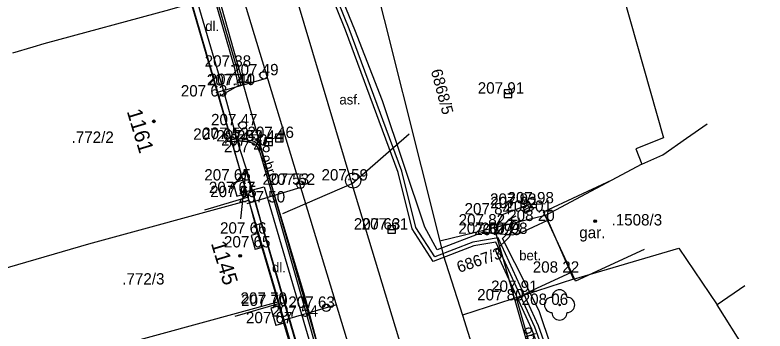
# Model space of a CAD drawing. Extents: x -524633 to -524336, y -1187893 to -1187683.
# Drawn here: x -524519.98 to -524470.48, y -1187820.09 to -1187799.22 of the extents above; entities that cross this region are included whole.
import ezdxf

# ---------------------------------------------------------------- set-up
doc = ezdxf.new("R2010")
doc.units = 0
for name, color, linetype in [('Hranice parcel', 7, 'Continuous'), ('Parcelní čísla', 7, 'Continuous'), ('Vrstva 1', 7, 'Continuous'), ('Vrstva 10', 7, 'Continuous'), ('Vrstva 11', 7, 'Continuous'), ('Vrstva 22', 7, 'Continuous'), ('Vrstva 24', 7, 'Continuous'), ('Vrstva 27', 7, 'Continuous'), ('Vrstva 28', 7, 'Continuous'), ('Vrstva 3', 7, 'Continuous'), ('Vrstva 36', 7, 'Continuous'), ('Vrstva 39', 7, 'Continuous'), ('Vrstva 4', 7, 'Continuous'), ('Vrstva 40', 7, 'Continuous'), ('Vrstva 41', 7, 'Continuous'), ('Vrstva 47', 7, 'Continuous'), ('Vrstva 5', 7, 'Continuous'), ('Vrstva 52', 7, 'Continuous'), ('Vrstva 53', 7, 'Continuous'), ('Vrstva 54', 7, 'Continuous'), ('Vrstva 55', 7, 'Continuous'), ('Vrstva 56', 7, 'Continuous'), ('Vrstva 58', 7, 'Continuous')]:
    doc.layers.add(name, color=color, linetype=linetype)

msp = doc.modelspace()

# ---------------------------------------------------------------- linework, layer by layer
at = {"layer": 'Hranice parcel'}
for p, q in [((-524504.56, -1187811.45), (-524508.34, -1187798.46)), ((-524478.61, -1187809.07), (-524484.96, -1187812.46)), ((-524502.57, -1187818.16), (-524504.56, -1187811.45)), ((-524484.96, -1187812.46), (-524491.95, -1187814.16)), ((-524484.96, -1187812.46), (-524484.74, -1187812.94)), ((-524484.74, -1187812.94), (-524483.13, -1187816.67)), ((-524483.13, -1187816.67), (-524490.45, -1187819.04)), ((-524500.33, -1187825.89), (-524502.57, -1187818.16)), ((-524470.48, -1187823.34), (-524473.64, -1187818.37))]:
    msp.add_line(p, q, dxfattribs=at)
for points in [[(-524504.01, -1187770.49), (-524496.85, -1187794.59), (-524491.95, -1187814.16)], [(-524480.71, -1187794.88), (-524477.19, -1187807.33), (-524479.01, -1187808.05), (-524478.61, -1187809.07)], [(-524508.34, -1187798.46), (-524509.78, -1187798.88), (-524518.07, -1187801.13)], [(-524518.07, -1187801.13), (-524518.81, -1187801.35), (-524520.15, -1187801.74)], [(-524478.61, -1187809.07), (-524477.23, -1187808.46), (-524475.66, -1187807.35), (-524474.304, -1187806.397)], [(-524526.11, -1187817.52), (-524521.55, -1187816.2), (-524515.1, -1187814.33), (-524504.56, -1187811.45)], [(-524491.95, -1187814.16), (-524491.72, -1187815.07), (-524490.45, -1187819.04)], [(-524483.13, -1187816.67), (-524476.17, -1187814.61), (-524473.64, -1187818.37)], [(-524471.818, -1187817.116), (-524473.64, -1187818.37)], [(-524502.57, -1187818.16), (-524513.11, -1187821.06), (-524515.74, -1187821.78), (-524520.23, -1187823.1), (-524526.74, -1187825.01)], [(-524490.45, -1187819.04), (-524486.12, -1187832.88), (-524481.69, -1187847.02)]]:
    msp.add_lwpolyline(points, dxfattribs=at)
at = {"layer": 'Vrstva 1'}
for p, q in [((-524505.37, -1187802.63), (-524505.37, -1187802.63)), ((-524503.56, -1187803.2), (-524503.56, -1187803.2)), ((-524505.23, -1187803.87), (-524505.23, -1187803.87)), ((-524505.08, -1187803.84), (-524505.08, -1187803.84)), ((-524506.54, -1187804.6), (-524506.54, -1187804.6)), ((-524487.44, -1187804.41), (-524487.44, -1187804.41)), ((-524504.95, -1187806.5), (-524504.95, -1187806.5)), ((-524505.72, -1187807.46), (-524505.72, -1187807.46)), ((-524505.13, -1187807.4), (-524505.13, -1187807.4)), ((-524504.19, -1187807.57), (-524504.19, -1187807.57)), ((-524503.24, -1187807.58), (-524503.24, -1187807.58)), ((-524502.53, -1187807.34), (-524502.53, -1187807.34)), ((-524503.88, -1187807.84), (-524503.88, -1187807.84)), ((-524503.69, -1187808.28), (-524503.69, -1187808.28)), ((-524504.99, -1187810.15), (-524504.99, -1187810.15)), ((-524497.66, -1187810.15), (-524497.66, -1187810.15)), ((-524501.14, -1187810.43), (-524501.14, -1187810.43)), ((-524501.14, -1187810.44), (-524501.14, -1187810.44)), ((-524504.69, -1187810.98), (-524504.69, -1187810.98)), ((-524504.6, -1187811.25), (-524504.6, -1187811.25)), ((-524502.72, -1187811.6), (-524502.72, -1187811.6)), ((-524484.98, -1187811.66), (-524484.98, -1187811.66)), ((-524486.13, -1187811.75), (-524486.13, -1187811.75)), ((-524486.11, -1187811.98), (-524486.11, -1187811.98)), ((-524487.81, -1187812.39), (-524487.81, -1187812.39)), ((-524485.11, -1187812.21), (-524485.11, -1187812.21)), ((-524488.2, -1187813.12), (-524488.2, -1187813.12)), ((-524484.93, -1187812.83), (-524484.93, -1187812.83)), ((-524503.95, -1187813.66), (-524503.95, -1187813.66)), ((-524495.12, -1187813.39), (-524495.12, -1187813.39)), ((-524495.1, -1187813.39), (-524495.1, -1187813.39)), ((-524488.22, -1187813.67), (-524488.22, -1187813.67)), ((-524486.72, -1187813.68), (-524486.72, -1187813.68)), ((-524488.27, -1187813.76), (-524488.27, -1187813.76)), ((-524487.17, -1187813.76), (-524487.17, -1187813.76)), ((-524503.69, -1187814.57), (-524503.69, -1187814.57)), ((-524483.31, -1187816.24), (-524483.31, -1187816.24)), ((-524482.99, -1187816.8), (-524482.99, -1187816.8)), ((-524486.06, -1187817.51), (-524486.06, -1187817.51)), ((-524486.98, -1187818.07), (-524486.98, -1187818.07)), ((-524502.6, -1187818.29), (-524502.6, -1187818.29)), ((-524502.56, -1187818.44), (-524502.56, -1187818.44)), ((-524499.44, -1187818.56), (-524499.44, -1187818.56)), ((-524484.04, -1187818.37), (-524484.04, -1187818.37)), ((-524502.24, -1187819.58), (-524502.24, -1187819.58)), ((-524500.55, -1187819.15), (-524500.55, -1187819.15))]:
    msp.add_line(p, q, dxfattribs=at)
at = {"layer": 'Vrstva 10'}
msp.add_line((-524506.539, -1187804.6), (-524505.229, -1187803.87), dxfattribs=at)
for points in [[(-524505.229, -1187803.87), (-524505.079, -1187803.84), (-524505.369, -1187802.63), (-524510.679, -1187784.37), (-524510.92, -1187783.49)], [(-524502.719, -1187811.6), (-524503.689, -1187808.28), (-524503.879, -1187807.84), (-524504.189, -1187807.57), (-524505.129, -1187807.4), (-524505.72, -1187807.46)], [(-524500.549, -1187819.15), (-524502.719, -1187811.6)], [(-524488.219, -1187813.67), (-524488.199, -1187813.12), (-524487.809, -1187812.39), (-524486.129, -1187811.75), (-524484.979, -1187811.66)], [(-524485.629, -1187822.8), (-524486.979, -1187818.07), (-524488.219, -1187813.67)], [(-524497.64, -1187829.21), (-524500.549, -1187819.15)]]:
    msp.add_lwpolyline(points, dxfattribs=at)
at = {"layer": 'Vrstva 11'}
for p, q in [((-524500.674, -1187819.186), (-524502.844, -1187811.636)), ((-524497.765, -1187829.246), (-524500.674, -1187819.186))]:
    msp.add_line(p, q, dxfattribs=at)
for points in [[(-524505.229, -1187803.87), (-524505.495, -1187802.663), (-524510.75, -1187784.44), (-524511.045, -1187783.524)], [(-524502.844, -1187811.636), (-524503.812, -1187808.324), (-524503.987, -1187807.919), (-524504.247, -1187807.692), (-524505.134, -1187807.531), (-524505.707, -1187807.589)], [(-524484.843, -1187812.789), (-524486.719, -1187813.68), (-524487.169, -1187813.76), (-524488.219, -1187813.67)], [(-524486.864, -1187818), (-524486.06, -1187817.51), (-524483.259, -1187816.217)], [(-524485.504, -1187822.764), (-524486.864, -1187818), (-524486.979, -1187818.07)]]:
    msp.add_lwpolyline(points, dxfattribs=at)
at = {"layer": 'Vrstva 22'}
msp.add_circle((-524484.04, -1187818.37), 0.05, dxfattribs=at)
for centre, start, end in [((-524484.04, -1187817.87), 0, 180), ((-524484.54, -1187818.37), 90, 270), ((-524483.54, -1187818.37), 270, 90), ((-524484.04, -1187818.87), 180, 0)]:
    msp.add_arc(centre, 0.5, start, end, dxfattribs=at)
at = {"layer": 'Vrstva 24'}
msp.add_lwpolyline([(-524486.389, -1187812.11), (-524486.299, -1187812.3), (-524485.75, -1187812.05), (-524485.84, -1187811.85), (-524486.389, -1187812.11)], dxfattribs=at)
at = {"layer": 'Vrstva 27'}
for p, q in [((-524487.69, -1187804.41), (-524487.19, -1187804.41)), ((-524503.489, -1187807.58), (-524502.989, -1187807.58)), ((-524502.78, -1187807.34), (-524502.28, -1187807.34)), ((-524495.369, -1187813.39), (-524494.869, -1187813.39))]:
    msp.add_line(p, q, dxfattribs=at)
for points in [[(-524487.69, -1187804.66), (-524487.19, -1187804.66), (-524487.19, -1187804.16), (-524487.69, -1187804.16)], [(-524502.78, -1187807.59), (-524502.28, -1187807.59), (-524502.28, -1187807.09), (-524502.78, -1187807.09)], [(-524503.489, -1187807.83), (-524502.989, -1187807.83), (-524502.989, -1187807.33), (-524503.489, -1187807.33)], [(-524495.369, -1187813.64), (-524494.869, -1187813.64), (-524494.869, -1187813.14), (-524495.369, -1187813.14)]]:
    msp.add_lwpolyline(points, close=True, dxfattribs=at)
msp.add_circle((-524497.66, -1187810.15), 0.5, dxfattribs=at)
at = {"layer": 'Vrstva 28'}
for centre in [(-524503.56, -1187803.2), (-524504.949, -1187806.5), (-524501.139, -1187810.43), (-524499.44, -1187818.56)]:
    msp.add_circle(centre, 0.25, dxfattribs=at)
at = {"layer": 'Vrstva 36'}
for p, q in [((-524487.198, -1187813.356), (-524487.198, -1187812.606)), ((-524486.697, -1187813.356), (-524486.697, -1187812.606))]:
    msp.add_line(p, q, dxfattribs=at)
at = {"layer": 'Vrstva 39'}
for centre, radius in [((-524510.814, -1187806.24), 0.09), ((-524510.814, -1187806.24), 0.0398), ((-524481.689, -1187812.836), 0.09), ((-524481.689, -1187812.836), 0.0398), ((-524505.113, -1187815.119), 0.09), ((-524505.113, -1187815.119), 0.0398)]:
    msp.add_circle(centre, radius, dxfattribs=at)
at = {"layer": 'Vrstva 5'}
for p, q in [((-524485.11, -1187812.21), (-524480.571, -1187810.113)), ((-524504.599, -1187811.25), (-524504.689, -1187810.98)), ((-524504.599, -1187811.25), (-524507.473, -1187812.11)), ((-524503.95, -1187813.66), (-524504.599, -1187811.25)), ((-524503.689, -1187814.57), (-524503.95, -1187813.66)), ((-524503.689, -1187814.57), (-524504.14, -1187814.702)), ((-524503.689, -1187814.57), (-524502.599, -1187818.29)), ((-524478.451, -1187814.703), (-524482.99, -1187816.8)), ((-524502.599, -1187818.29), (-524505.477, -1187819.138)), ((-524502.599, -1187818.29), (-524502.559, -1187818.44)), ((-524502.559, -1187818.44), (-524502.239, -1187819.58)), ((-524502.239, -1187819.58), (-524502.769, -1187819.729)), ((-524500.319, -1187826.01), (-524502.239, -1187819.58))]:
    msp.add_line(p, q, dxfattribs=at)
for points in [[(-524508.339, -1187798.39), (-524506.539, -1187804.6)], [(-524506.539, -1187804.6), (-524505.72, -1187807.46)], [(-524505.72, -1187807.46), (-524504.937, -1187810.133), (-524504.689, -1187810.98)], [(-524504.937, -1187810.133), (-524505.588, -1187810.322)], [(-524505.588, -1187810.322), (-524505.337, -1187811.186)], [(-524505.337, -1187811.186), (-524504.689, -1187810.98)], [(-524482.99, -1187816.8), (-524483.259, -1187816.217), (-524484.843, -1187812.789), (-524485.11, -1187812.21)], [(-524503.95, -1187813.66), (-524504.404, -1187813.782)], [(-524504.404, -1187813.782), (-524504.14, -1187814.702)], [(-524502.559, -1187818.44), (-524503.089, -1187818.589)], [(-524503.089, -1187818.589), (-524502.769, -1187819.729)]]:
    msp.add_lwpolyline(points, dxfattribs=at)
at = {"layer": 'Vrstva 52'}
for points in [[(-524483.491, -1187825.944), (-524485.662, -1187819.843), (-524488.238, -1187814.221), (-524489.704, -1187814.458), (-524492.375, -1187815.51), (-524493.76, -1187813.348), (-524494.687, -1187809.612), (-524498.159, -1187800.215), (-524501.96, -1187790.797), (-524504.415, -1187784.139), (-524505.106, -1187780.207), (-524505.87, -1187777.458), (-524505.484, -1187776.552)], [(-524496.398, -1187840.378), (-524494.948, -1187840.08), (-524494.688, -1187839.875), (-524487.612, -1187837.45), (-524481.715, -1187835.492), (-524481.43, -1187834.708), (-524482.034, -1187831.222), (-524482.934, -1187828.39), (-524483.247, -1187825.883), (-524485.431, -1187819.747), (-524488.09, -1187813.944), (-524489.77, -1187814.215), (-524492.275, -1187815.202), (-524493.527, -1187813.248), (-524494.448, -1187809.538), (-524497.926, -1187800.125), (-524501.727, -1187790.707), (-524504.173, -1187784.072), (-524504.862, -1187780.152), (-524505.655, -1187777.244), (-524505.315, -1187776.503)], [(-524486.932, -1187812.511), (-524487.392, -1187812.716), (-524488.246, -1187813.711), (-524489.008, -1187813.544), (-524492.116, -1187814.721), (-524492.941, -1187813.226), (-524495.729, -1187804.887), (-524497.543, -1187800.186), (-524501.372, -1187790.808), (-524503.625, -1187784.398), (-524504.544, -1187780.063), (-524504.509, -1187778.639), (-524505.44, -1187777.03), (-524505.101, -1187776.436)], [(-524486.634, -1187812.757), (-524487.014, -1187813.084), (-524487.375, -1187813.9), (-524488.263, -1187814.766), (-524485.893, -1187819.939), (-524483.735, -1187826.005), (-524483.424, -1187828.498), (-524482.522, -1187831.332), (-524481.946, -1187834.662), (-524482.103, -1187835.094), (-524487.772, -1187836.976), (-524494.962, -1187839.441), (-524496.019, -1187838.148), (-524497.136, -1187835.732)], [(-524496.323, -1187840.62), (-524494.794, -1187840.283), (-524494.551, -1187840.092), (-524487.422, -1187837.952), (-524481.428, -1187835.884), (-524480.97, -1187834.874), (-524481.585, -1187831.318), (-524482.69, -1187828.33), (-524483.003, -1187825.824), (-524485.394, -1187818.765), (-524487.797, -1187813.983), (-524487.557, -1187813.745), (-524487.237, -1187812.921), (-524486.827, -1187812.738)]]:
    msp.add_lwpolyline(points, dxfattribs=at)
at = {"layer": 'Vrstva 53'}
for points in [[(-524525.446, -1187746.167), (-524511.928, -1187773.746), (-524506.531, -1187798.067), (-524502.9, -1187810.999), (-524500.825, -1187817.931), (-524498.784, -1187825.686)], [(-524518.67, -1187775.66), (-524515.01, -1187774.04), (-524512.56, -1187782.53), (-524507.91, -1187798.49), (-524506.24, -1187804.15), (-524505.21, -1187807.9), (-524504.64, -1187809.64)], [(-524504.23, -1187813.14), (-524503.71, -1187812.98), (-524504.64, -1187809.64), (-524505.15, -1187809.85)], [(-524503.71, -1187812.98), (-524502.16, -1187818.34), (-524500.57, -1187823.77)]]:
    msp.add_lwpolyline(points, dxfattribs=at)
at = {"layer": 'Vrstva 54'}
for p, q in [((-524488.745, -1187851.342), (-524510.722, -1187778.991)), ((-524503.308, -1187803.397), (-524506.737, -1187804.361)), ((-524501.114, -1187810.622), (-524504.676, -1187811.688)), ((-524498.76, -1187818.372), (-524502.372, -1187819.42))]:
    msp.add_line(p, q, dxfattribs=at)
at = {"layer": 'Vrstva 55'}
for p, q in [((-524502.4, -1187794.79), (-524497.74, -1187810.36)), ((-524497.74, -1187810.36), (-524493.97, -1187807.076)), ((-524497.74, -1187810.36), (-524502.323, -1187812.358)), ((-524497.74, -1187810.36), (-524485.38, -1187851.41))]:
    msp.add_line(p, q, dxfattribs=at)
at = {"layer": 'Vrstva 56'}
msp.add_lwpolyline([(-524504.89, -1187810.93), (-524503.54, -1187810.56), (-524499.57, -1187824.08)], dxfattribs=at)
at = {"layer": 'Vrstva 58'}
for points in [[(-524504.756, -1187809.419), (-524505.733, -1187810.699)], [(-524504.756, -1187809.419), (-524505.097, -1187812.688)], [(-524497.136, -1187835.732), (-524501.064, -1187822.132), (-524504.756, -1187809.419)]]:
    msp.add_lwpolyline(points, dxfattribs=at)

# ---------------------------------------------------------------- texts
at = {"layer": 'Parcelní čísla'}
for s, rotation, p in [('6868/5', 285, (-524492.543, -1187802.895)), ('6867/3', 19, (-524490.669, -1187816.258))]:
    msp.add_text(s, height=0.75, rotation=rotation, dxfattribs=at).set_placement(p)
for s, p in [('.772/2', (-524516.249, -1187807.663)), ('.1508/3', (-524480.612, -1187813.121)), ('.772/3', (-524512.905, -1187817.023))]:
    msp.add_text(s, height=0.75, dxfattribs=at).set_placement(p)
at = {"layer": 'Vrstva 3'}
for s, p in [('207.38', (-524507.464, -1187802.63)), ('207.91', (-524489.44, -1187804.41)), ('207 63 ', (-524509.04, -1187804.6)), ('207 61 ', (-524508.22, -1187807.46)), ('207 65 ', (-524507.49, -1187810.15)), ('207.59', (-524499.754, -1187810.15)), ('207 98 ', (-524487.48, -1187811.66)), ('207 63 ', (-524497.62, -1187813.39)), ('207 66 ', (-524506.45, -1187813.66)), ('207 80 ', (-524490.72, -1187813.67)), ('208 22 ', (-524485.81, -1187816.24)), ('207 91 ', (-524488.56, -1187817.51)), ('207 70 ', (-524505.06, -1187818.44))]:
    msp.add_text(s, height=0.75, dxfattribs=at).set_placement(p)
at = {"layer": 'Vrstva 4'}
for s, p in [('207.49', (-524505.654, -1187803.2)), ('207.44', (-524507.324, -1187803.87)), ('207.40', (-524507.204, -1187803.84)), ('207.47', (-524507.044, -1187806.5)), ('207 52 ', (-524507.63, -1187807.4)), ('207.46', (-524504.641, -1187807.34)), ('207 52 ', (-524506.69, -1187807.57)), ('207 50 ', (-524506.38, -1187807.84)), ('207.44', (-524505.334, -1187807.58)), ('207 48 ', (-524506.19, -1187808.28)), ('207 53 ', (-524503.64, -1187810.43)), ('207.52', (-524503.234, -1187810.44)), ('207 67 ', (-524507.19, -1187810.98)), ('207 65 ', (-524507.1, -1187811.25)), ('207 50 ', (-524505.22, -1187811.6)), ('207 93 ', (-524488.63, -1187811.75)), ('207 92 ', (-524488.61, -1187811.98)), ('207 84 ', (-524490.31, -1187812.39)), ('208 01 ', (-524487.61, -1187812.21)), ('208 20 ', (-524487.43, -1187812.83)), ('207.61', (-524497.1, -1187813.39)), ('207 82 ', (-524490.7, -1187813.12)), ('207 93 ', (-524489.67, -1187813.76)), ('207 98 ', (-524489.22, -1187813.68)), ('207 65 ', (-524506.19, -1187814.57)), ('207 70 ', (-524505.1, -1187818.29)), ('207 80 ', (-524489.48, -1187818.07)), ('208 06 ', (-524486.54, -1187818.37)), ('207 63 ', (-524501.94, -1187818.56)), ('207 54 ', (-524503.05, -1187819.15)), ('207 67 ', (-524504.74, -1187819.58))]:
    msp.add_text(s, height=0.75, dxfattribs=at).set_placement(p)
at = {"layer": 'Vrstva 40'}
for s, p in [('dl.', (-524507.426, -1187800.276)), ('asf.', (-524498.572, -1187805.128)), ('bet.', (-524486.706, -1187815.424)), ('dl.', (-524503.017, -1187816.22))]:
    msp.add_text(s, height=0.65, dxfattribs=at).set_placement(p)
for rotation, p in [(287.4555, (-524503.741, -1187808.56)), (288.0973, (-524486.447, -1187819.921))]:
    msp.add_text('obr.', height=0.65, rotation=rotation, dxfattribs=at).set_placement(p)
at = {"layer": 'Vrstva 41'}
msp.add_text('gar.', height=0.75, dxfattribs=at).set_placement((-524482.74, -1187813.961))
at = {"layer": 'Vrstva 47'}
for s, p in [('1161', (-524512.614, -1187805.58)), ('1145', (-524507.058, -1187814.303))]:
    msp.add_text(s, height=1, rotation=286.8364, dxfattribs=at).set_placement(p)

doc.saveas('drawing.dxf')
